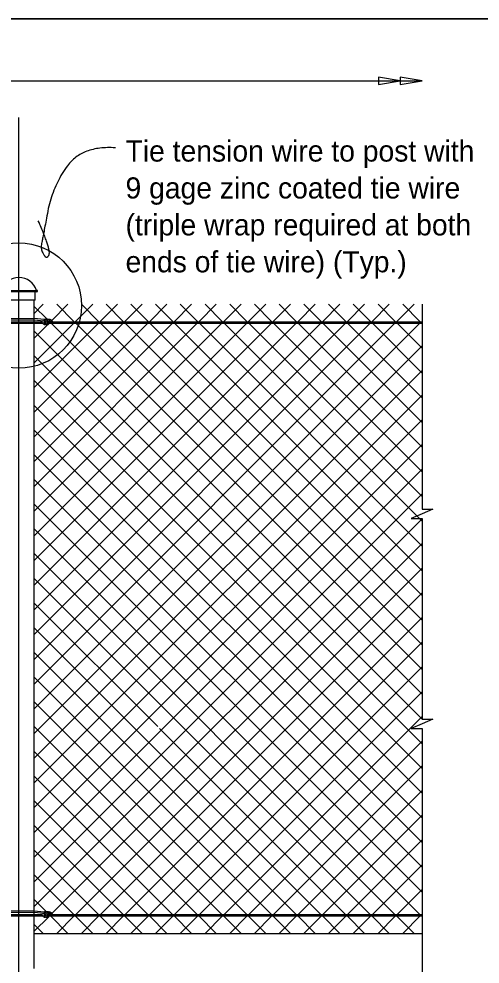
# Model space of a CAD drawing. Extents: x 0 to 41.1, y 0 to 25.9.
# Drawn here: x 24.62 to 29.01, y 16.93 to 25.95 of the extents above; entities that cross this region are included whole.
import ezdxf

# ---------------------------------------------------------------- set-up
doc = ezdxf.new("R2010")
doc.units = 0
for name, color, linetype in [('ActivePts-ConstElements', 7, 'Continuous'), ('CL_Major', 7, 'Continuous'), ('Dimension', 7, 'Continuous'), ('Miscellaneous', 7, 'Continuous'), ('Miscellaneous1', 7, 'Continuous'), ('SteelMisc', 7, 'Continuous'), ('SteelMisc_h', 7, 'Continuous'), ('SupstrConc', 7, 'Continuous')]:
    doc.layers.add(name, color=color, linetype=linetype)

msp = doc.modelspace()

# ---------------------------------------------------------------- linework, layer by layer
at = {"layer": 'ActivePts-ConstElements'}
msp.add_lwpolyline([(0, 0), (41.0506, 0), (41.0506, 25.9461), (0, 25.9461)], close=True, dxfattribs=at)
at = {"layer": 'CL_Major'}
msp.add_line((24.6151, 11.3358), (24.6151, 25.0052), dxfattribs=at)
at = {"layer": 'Dimension'}
for points in [[(13.615, 25.3556), (15.0787, 25.3556), (15.0787, 25.4589), (15.1237, 25.3556), (15.1687, 25.2523), (15.1687, 25.3556), (28.4596, 25.3556)], [(28.4596, 23.2265), (28.4596, 21.2702), (28.5629, 21.2702), (28.4596, 21.2252), (28.3562, 21.1802), (28.4596, 21.1802), (28.4596, 20.2867)], [(28.4596, 20.2867), (28.4596, 19.2689), (28.5629, 19.2689), (28.4596, 19.2239), (28.3562, 19.1789), (28.4596, 19.1789), (28.4596, 16.9746)], [(28.4596, 17.2246), (28.4596, 15.3737), (28.5629, 15.3737), (28.4596, 15.3287), (28.3562, 15.2837), (28.4596, 15.2837), (28.4596, 13.4788)]]:
    msp.add_lwpolyline(points, dxfattribs=at)
for points in [[(28.2513, 25.3556), (28.0431, 25.3909), (28.0431, 25.3203)], [(28.4596, 25.3556), (28.2513, 25.3909), (28.2513, 25.3203)]]:
    msp.add_lwpolyline(points, close=True, dxfattribs=at)
msp.add_circle((24.615, 23.212), 0.5976, dxfattribs=at)
msp.add_open_spline([(25.5348, 24.717), (25.216, 24.7369), (24.9346, 24.348), (24.8419, 23.852), (24.8201, 23.7498), (24.8799, 23.6501), (24.9246, 23.7397), (24.8002, 24.019)], degree=2, dxfattribs=at)
at = {"layer": 'Miscellaneous'}
for p, q in [((24.7609, 23.1379), (24.8475, 23.2245)), ((24.7609, 23.2036), (24.8832, 23.0814)), ((24.928, 23.0694), (25.0832, 23.2245)), ((24.9757, 23.2245), (25.1424, 23.0578)), ((25.1522, 23.0578), (25.3189, 23.2245)), ((25.2114, 23.2245), (25.3781, 23.0578)), ((25.3879, 23.0578), (25.5546, 23.2245)), ((25.4471, 23.2245), (25.6138, 23.0578)), ((25.6236, 23.0578), (25.7903, 23.2245)), ((25.6828, 23.2245), (25.8495, 23.0578)), ((25.8593, 23.0578), (26.026, 23.2245)), ((25.9185, 23.2245), (26.0852, 23.0578)), ((26.095, 23.0578), (26.2617, 23.2245)), ((26.1542, 23.2245), (26.3209, 23.0578)), ((26.3307, 23.0578), (26.4974, 23.2245)), ((26.3899, 23.2245), (26.5566, 23.0578)), ((26.5664, 23.0578), (26.7331, 23.2245)), ((26.6257, 23.2245), (26.7923, 23.0578)), ((26.8021, 23.0578), (26.9688, 23.2245)), ((26.8614, 23.2245), (27.028, 23.0578)), ((27.0378, 23.0578), (27.2045, 23.2245)), ((27.0971, 23.2245), (27.2637, 23.0578)), ((27.2735, 23.0578), (27.4402, 23.2245)), ((27.3328, 23.2245), (27.4994, 23.0578)), ((27.5092, 23.0578), (27.6759, 23.2245)), ((27.5685, 23.2245), (27.7351, 23.0578)), ((27.7449, 23.0578), (27.9116, 23.2245)), ((27.8042, 23.2245), (27.9708, 23.0578)), ((27.9806, 23.0578), (28.1473, 23.2245)), ((28.0399, 23.2245), (28.2065, 23.0578)), ((28.2163, 23.0578), (28.383, 23.2245)), ((28.2756, 23.2245), (28.4422, 23.0578)), ((24.7609, 20.0738), (27.7302, 23.0431)), ((24.7609, 20.5452), (27.2588, 23.0431)), ((24.7609, 21.0166), (26.7874, 23.0431)), ((24.7609, 21.488), (26.316, 23.0431)), ((24.7609, 19.6024), (28.2016, 23.0431)), ((24.7609, 21.7237), (26.0803, 23.0431)), ((24.7609, 21.2523), (26.5517, 23.0431)), ((24.7609, 20.7809), (27.0231, 23.0431)), ((24.7609, 20.3095), (27.4945, 23.0431)), ((24.7609, 19.8381), (27.9659, 23.0431)), ((24.7609, 19.3667), (28.4373, 23.0431)), ((24.7609, 21.9594), (25.8446, 23.0431)), ((24.7609, 22.4308), (25.3732, 23.0431)), ((24.7609, 22.6665), (25.1375, 23.0431)), ((24.7609, 22.9022), (24.8904, 23.0317)), ((24.7653, 22.1995), (25.6089, 23.0431)), ((24.9165, 23.0578), (24.921, 23.0623)), ((24.9214, 23.0431), (28.4595, 19.505)), ((25.1572, 23.0431), (28.4595, 19.7407)), ((25.3929, 23.0431), (28.4595, 19.9764)), ((25.6286, 23.0431), (28.4595, 20.2121)), ((25.8643, 23.0431), (28.4595, 20.4478)), ((26.1, 23.0431), (28.4595, 20.6835)), ((26.3357, 23.0431), (28.4595, 20.9192)), ((26.5714, 23.0431), (28.4595, 21.1549)), ((26.8071, 23.0431), (28.4595, 21.3906)), ((27.0428, 23.0431), (28.4595, 21.6263)), ((27.2785, 23.0431), (28.4595, 21.862)), ((27.5142, 23.0431), (28.4595, 22.0977)), ((27.7499, 23.0431), (28.4595, 22.3334)), ((27.9856, 23.0431), (28.4595, 22.5691)), ((28.2213, 23.0431), (28.4595, 22.8048)), ((24.7609, 22.9679), (28.4595, 19.2693)), ((24.7609, 19.131), (28.4595, 22.8296)), ((24.7609, 22.7322), (28.4595, 19.0336)), ((24.7609, 18.8953), (28.4595, 22.5939)), ((24.7609, 22.4965), (28.4595, 18.7979)), ((24.7609, 18.6596), (28.4595, 22.3582)), ((24.7609, 22.2608), (28.4595, 18.5622)), ((24.7609, 18.4239), (28.4595, 22.1225)), ((24.7609, 22.0251), (28.4595, 18.3265)), ((24.7609, 18.1882), (28.4595, 21.8868)), ((24.7609, 21.7894), (28.4595, 18.0908)), ((24.7609, 17.9525), (28.4595, 21.6511)), ((24.7609, 21.5537), (28.4595, 17.8551)), ((24.7609, 17.7168), (28.4595, 21.4154)), ((24.7609, 21.318), (28.4595, 17.6194)), ((24.7609, 17.4811), (28.4595, 21.1797)), ((24.7609, 21.0823), (28.4373, 17.4059)), ((24.9303, 17.4148), (28.4595, 20.944)), ((24.7609, 20.8466), (28.2016, 17.4059)), ((25.1572, 17.4059), (28.4595, 20.7083)), ((24.7609, 20.6109), (27.9659, 17.4059)), ((25.3929, 17.4059), (28.4595, 20.4726)), ((24.7609, 20.3752), (25.9395, 19.1966)), ((25.6286, 17.4059), (28.4595, 20.2369)), ((24.7609, 20.1395), (27.4945, 17.4059)), ((25.8643, 17.4059), (28.4595, 20.0012)), ((24.7609, 19.9038), (27.2588, 17.4059)), ((26.1, 17.4059), (28.4595, 19.7655)), ((24.7609, 19.6681), (27.0231, 17.4059)), ((26.3357, 17.4059), (28.4595, 19.5298)), ((24.7609, 19.4324), (26.7874, 17.4059)), ((26.5714, 17.4059), (28.4595, 19.2941)), ((24.7609, 19.1967), (26.5517, 17.4059)), ((25.9572, 19.1789), (27.7302, 17.4059)), ((26.8071, 17.4059), (28.4595, 19.0584)), ((24.7609, 18.961), (26.316, 17.4059)), ((27.0428, 17.4059), (28.4595, 18.8227)), ((24.7609, 18.7253), (26.0803, 17.4059)), ((27.2785, 17.4059), (28.4595, 18.587)), ((24.7609, 18.4896), (25.8446, 17.4059)), ((27.5142, 17.4059), (28.4595, 18.3513)), ((24.7609, 18.2539), (25.6089, 17.4059)), ((27.7499, 17.4059), (28.4595, 18.1156)), ((24.7609, 18.0182), (25.3732, 17.4059)), ((27.9856, 17.4059), (28.4595, 17.8799)), ((24.7609, 17.7825), (25.1375, 17.4059)), ((28.2213, 17.4059), (28.4595, 17.6442)), ((24.7609, 17.5468), (24.8783, 17.4294)), ((24.7609, 17.2454), (24.8992, 17.3837)), ((24.7641, 17.3078), (24.8475, 17.2245)), ((24.9165, 17.3912), (25.0832, 17.2245)), ((24.9757, 17.2245), (25.1424, 17.3912)), ((25.1522, 17.3912), (25.3189, 17.2245)), ((25.2114, 17.2245), (25.3781, 17.3912)), ((25.3879, 17.3912), (25.5546, 17.2245)), ((25.4471, 17.2245), (25.6138, 17.3912)), ((25.6236, 17.3912), (25.7903, 17.2245)), ((25.6828, 17.2245), (25.8495, 17.3912)), ((25.8593, 17.3912), (26.026, 17.2245)), ((25.9185, 17.2245), (26.0852, 17.3912)), ((26.095, 17.3912), (26.2617, 17.2245)), ((26.1542, 17.2245), (26.3209, 17.3912)), ((26.3307, 17.3912), (26.4974, 17.2245)), ((26.3899, 17.2245), (26.5566, 17.3912)), ((26.5664, 17.3912), (26.7331, 17.2245)), ((26.6257, 17.2245), (26.7923, 17.3912)), ((26.8021, 17.3912), (26.9688, 17.2245)), ((26.8614, 17.2245), (27.028, 17.3912)), ((27.0378, 17.3912), (27.2045, 17.2245)), ((27.0971, 17.2245), (27.2637, 17.3912)), ((27.2735, 17.3912), (27.4402, 17.2245)), ((27.3328, 17.2245), (27.4994, 17.3912)), ((27.5092, 17.3912), (27.6759, 17.2245)), ((27.5685, 17.2245), (27.7351, 17.3912)), ((27.7449, 17.3912), (27.9116, 17.2245)), ((27.8042, 17.2245), (27.9708, 17.3912)), ((27.9806, 17.3912), (28.1473, 17.2245)), ((28.0399, 17.2245), (28.2065, 17.3912)), ((28.2163, 17.3912), (28.383, 17.2245)), ((28.2756, 17.2245), (28.4422, 17.3912))]:
    msp.add_line(p, q, dxfattribs=at)
at = {"layer": 'Miscellaneous1'}
msp.add_lwpolyline([(0, 25.9461), (41.0506, 25.9461), (41.0506, 0), (0, 0)], close=True, dxfattribs=at)
at = {"layer": 'SteelMisc'}
for p, q in [((24.4427, 23.3564), (24.7873, 23.3564)), ((24.7873, 23.3442), (24.4427, 23.3442)), ((24.7691, 23.2645), (24.461, 23.2645)), ((24.7609, 16.8894), (24.7609, 23.2644)), ((24.7691, 23.2645), (24.7691, 23.3442)), ((24.4692, 23.0904), (24.7604, 23.0921)), ((24.4692, 23.0759), (24.7604, 23.0776)), ((24.7604, 23.0921), (24.8547, 23.081)), ((24.7604, 23.0776), (24.8525, 23.0682)), ((24.7609, 23.0578), (24.8413, 23.0578)), ((24.7609, 23.0431), (24.8439, 23.0431)), ((24.9067, 23.0431), (28.4595, 23.0431)), ((24.9116, 23.0578), (24.9269, 23.0578)), ((24.9353, 23.0578), (28.4595, 23.0578)), ((24.4692, 17.4385), (24.7604, 17.4402)), ((24.4692, 17.424), (24.7604, 17.4257)), ((24.7604, 17.4402), (24.8547, 17.4291)), ((24.7604, 17.4257), (24.8525, 17.4163)), ((24.7609, 17.4059), (24.8413, 17.4059)), ((24.9116, 17.4059), (24.9269, 17.4059)), ((24.9353, 17.4059), (28.4595, 17.4059)), ((24.7609, 17.3912), (24.8439, 17.3912)), ((24.9059, 17.3912), (28.4595, 17.3912))]:
    msp.add_line(p, q, dxfattribs=at)
msp.add_arc((24.7872, 23.3502), 0.00613, 271.1647, 88.8353, dxfattribs=at)
for centre, major_axis, ratio, start_param, end_param in [((24.6157, 23.3154), (0.1711, 0), 0.957868, 0.252602, 2.888574), ((24.8556, 23.0562), (0.0303, -0.0108), 0.724765, 6.241815, 8.212701), ((24.8691, 23.0544), (-0.0295, 0), 0.957868, 2.243629, 5.062245), ((24.8879, 23.0598), (-0.023, 0), 0.957868, 3.312645, 4.992926), ((24.9004, 23.0453), (-0.0373, 0), 0.957868, 3.175144, 4.79635), ((24.8661, 23.0543), (-0.0251, 0), 0.957868, 0.055352, 0.751829), ((24.8661, 23.0543), (-0.0251, 0), 0.957868, 5.673972, 5.875498), ((24.8732, 23.0664), (-0.0391, 0), 0.957868, 0.863445, 1.200597), ((24.8506, 23.0433), (0.0259, 0), 0.957868, 0.655696, 1.505671), ((24.8663, 23.0556), (-0.0119, 0), 0.957868, 5.149694, 6.840495), ((24.8663, 23.0556), (-0.0119, 0), 0.957868, 0.560069, 0.643501), ((24.8646, 23.0498), (0.00795, 0), 0.957868, 3.252108, 6.425997), ((24.8658, 23.0476), (-0.0206, -0.0021), 0.798607, 1.063032, 2.950031), ((24.859, 23.0521), (0.0139, 0), 0.957868, 5.660958, 7.342751), ((24.8792, 23.0476), (-0.0206, -0.0021), 0.798607, 1.063032, 1.956656), ((24.8853, 23.0533), (-0.0231, 0), 0.957868, 1.403365, 2.503632), ((24.8867, 23.0573), (0.0249, 0), 0.957868, 5.476514, 6.557353), ((24.8792, 23.0056), (0.0724, 0), 0.957868, 0.631079, 1.121037), ((24.8661, 17.4024), (-0.0251, 0), 0.957868, 0.055352, 0.751829), ((24.8661, 17.4024), (-0.0251, 0), 0.957868, 5.673972, 5.875498), ((24.8556, 17.4043), (0.0303, -0.0108), 0.724765, 6.241815, 8.212701), ((24.8506, 17.3914), (0.0259, 0), 0.957868, 0.655696, 1.505671), ((24.8663, 17.4036), (-0.0119, 0), 0.957868, 5.149694, 6.840495), ((24.8663, 17.4036), (-0.0119, 0), 0.957868, 0.560069, 0.643501), ((24.8646, 17.3979), (0.00795, 0), 0.957868, 3.252108, 6.425997), ((24.8691, 17.4025), (-0.0295, 0), 0.957868, 2.243629, 5.062245), ((24.859, 17.4002), (0.0139, 0), 0.957868, 5.660958, 7.342751), ((24.8879, 17.4079), (-0.023, 0), 0.957868, 3.312645, 4.992926), ((24.9004, 17.3934), (-0.0373, 0), 0.957868, 3.175144, 4.79635), ((24.8867, 17.4054), (0.0249, 0), 0.957868, 5.476514, 6.557353), ((24.8792, 17.3537), (0.0724, 0), 0.957868, 0.631079, 1.121037), ((24.8732, 17.4144), (-0.0391, 0), 0.957868, 0.863445, 1.200597), ((24.8658, 17.3957), (-0.0206, -0.0021), 0.798607, 1.063032, 2.950031), ((24.8792, 17.3957), (-0.0206, -0.0021), 0.798607, 1.063032, 1.956656), ((24.8853, 17.4014), (-0.0231, 0), 0.957868, 1.403365, 2.503632)]:
    msp.add_ellipse(centre, major_axis=major_axis, ratio=ratio, start_param=start_param, end_param=end_param, dxfattribs=at)
at = {"layer": 'SteelMisc_h'}
for p, q in [((24.4692, 23.0578), (24.7609, 23.0578)), ((24.4692, 23.0431), (24.7609, 23.0431)), ((24.4692, 17.4059), (24.7609, 17.4059)), ((24.4692, 17.3912), (24.7609, 17.3912))]:
    msp.add_line(p, q, dxfattribs=at)
at = {"layer": 'SupstrConc'}
for q in [(28.4595, 17.2245), (26.002, 17.2245)]:
    msp.add_line((24.7609, 17.2245), q, dxfattribs=at)

# ---------------------------------------------------------------- texts
at = {"layer": 'Dimension'}
for s, p in [('Tie tension wire to post with ', (25.632, 24.5853)), ('9 gage zinc coated tie wire ', (25.632, 24.2333)), ('(triple wrap required at both ', (25.632, 23.8813)), ('ends of tie wire) (Typ.)', (25.632, 23.5293))]:
    msp.add_text(s, height=0.2016, dxfattribs=at).set_placement(p)

doc.saveas('drawing.dxf')
